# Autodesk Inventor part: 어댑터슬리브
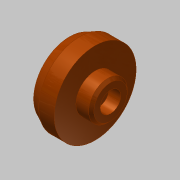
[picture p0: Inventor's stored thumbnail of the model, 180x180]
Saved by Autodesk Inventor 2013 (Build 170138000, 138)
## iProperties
Created: 2016-06
Part Number: 어댑터슬리브
Material: 강철, 탄소
Document SubType Name: Modeling
Designer: mduedu
Density: 7.87 g/cm^3
Author: mduedu
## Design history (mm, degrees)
sketch "스케치2"
  geometry: L1 (0, 0)-(0, 14); L2 (0, 14)-(-4, 16); L3 (-4, 16)-(-10, 16); L4 (-10, 16)-(-10, 7.5); L5 (-10, 7.5)-(-16, 7.5); L6 (-16, 7.5)-(-16, 0); L7 (-16, 0)-(0, 0)
  constraints: 14 end point, 4 parallel, 1 perpendicular, 1 vertical
  dimensions: "d0" = 32 diameter of L3 L7; "d2" = 28 diameter of L1.end L7; "d3" = 6 distance of L2.end L3.end; "d4" = 6 distance of L4.end L5.end; "d5" = 15 diameter of L5 L7; "d6" = 16 distance between parallel lines of L6 L1
revolve "회전1" sketch "스케치2" stored, may be unused: angle "d7" = 90 deg
sketch "스케치3"
  geometry: L1 (-16, -7.5)-(-16, 7.5) reference; L2 (-16, 7.5)-(-10, 7.5) reference; L3 (-10, 7.5)-(-10, 16) reference; L4 (-10, 16)-(-4, 16) reference; L5 (-4, 16)-(0, 14) reference; L6 (0, 14)-(0, -14) reference; L7 (0, -14)-(-4, -16) reference; L8 (-4, -16)-(-10, -16) reference; L9 (-10, -16)-(-10, -7.5) reference; L10 (-10, -7.5)-(-16, -7.5) reference; L11 (0, 10)-(-5, 10); L12 (-5, 10)-(-5, 8); L13 (-5, 8)-(-7, 6); L14 (-7, 6)-(-7, 0); L15 (-7, 0)-(0, 0); L16 (0, 10)-(0, 0)
  constraints: 12 end point, 3 parallel, 2 perpendicular, 1 point on line
  dimensions: "d8" = 20 diameter of L11 L15; "d10" = 16 diameter of L12.end L15; "d11" = 12 diameter of L13.end L15; "d12" = 9 distance between parallel lines of L14 L1; "d13" = 2 distance between parallel lines of L12 L14
revolve "회전2" sketch "스케치3" stored, may be unused: angle "d14" = 90 deg
chamfer "모따기1" distance "d15" = 1; stored, may be unused: second distance "d16" = 2, angle "d17" = 45 deg
sketch "스케치4"
  geometry: 2 further points
  constraints: 1 coincident
sketch "스케치5"
  geometry: 1 further point
hole "구멍1" sketch "스케치5" at (0, 0) diameter "d18" = 4.5; stored, may be unused: countersink angle "d22" = 90 deg, drill point angle "d24" = 0 deg; dims "d19" = 6, "d20" = 8, "d21" = 4.6, "d23" = 8
node "솔리드1"
node "절단 모서리 투영1"
